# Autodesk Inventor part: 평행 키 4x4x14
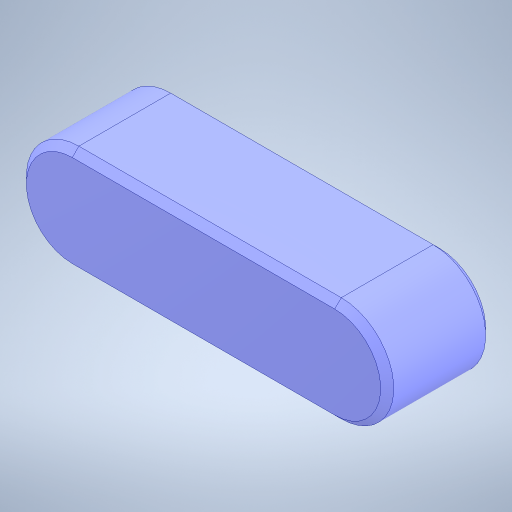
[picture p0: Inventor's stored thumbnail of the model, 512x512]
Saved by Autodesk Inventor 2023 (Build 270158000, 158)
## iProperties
Created: 2026-03
Part Number: 평행 키 4x4x14
Material: 강철, 연강
Description: 키 및 해당 키홈
Document SubType Name: Modeling
Designer: home
Density: 7.85 g/cm^3
Appearance: 기본값
Author: jhkim
Sending System: Autodesk Inventor 2026
Preprocessor: ST-DEVELOPER v20.1
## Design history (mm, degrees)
feature "Solid1"
node "솔리드1"
